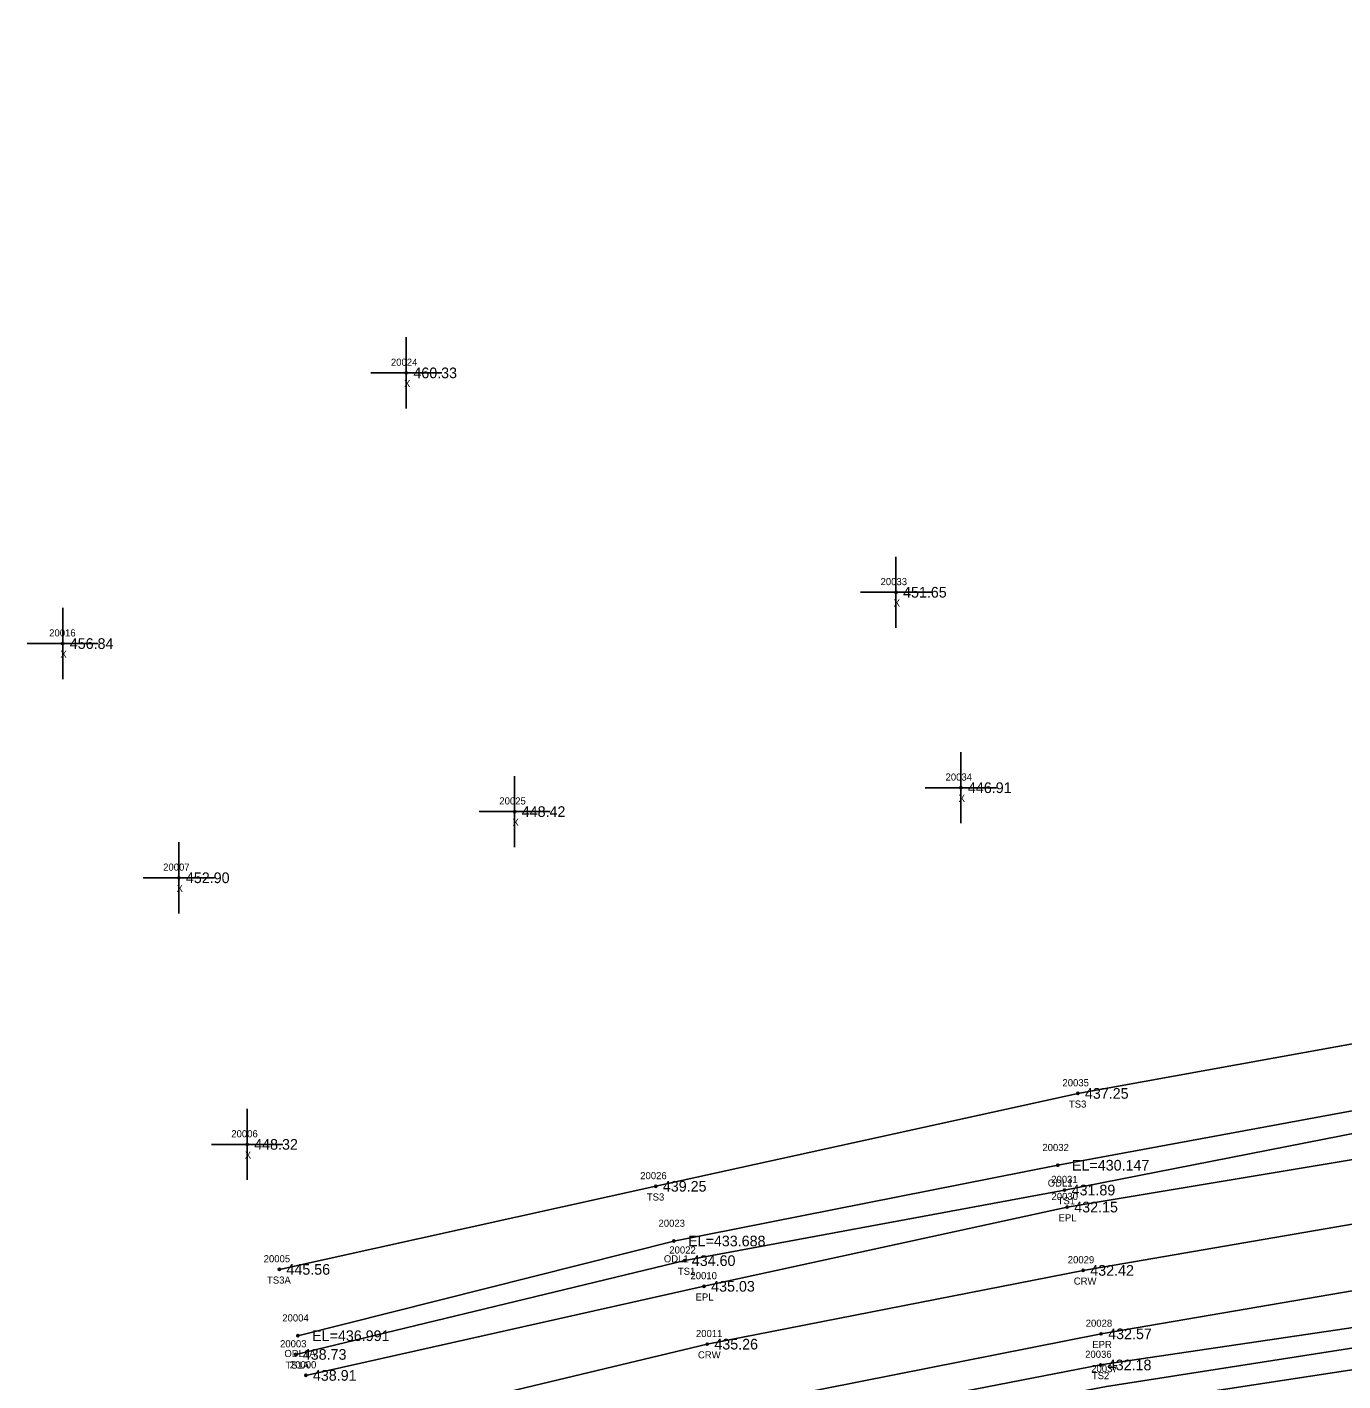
# Model space of a CAD drawing. Extents: x 2116373 to 2118139, y 979529 to 981026.
# Drawn here: x 2116373 to 2116558, y 979638.1 to 979828.4 of the extents above; entities that cross this region are included whole.
import ezdxf

# ---------------------------------------------------------------- set-up
doc = ezdxf.new("R2010")
doc.units = 0
for name, color, linetype in [('RD_DTM_BkLn1', 7, 'Continuous'), ('RD_DTM_BkLn2', 7, 'Continuous'), ('RD_DTM_BkLn_txCode', 7, 'Continuous'), ('RD_EX_H2O', 7, 'Continuous'), ('RD_EX_H2O_txCode', 7, 'Continuous'), ('RD_EX_Misc', 7, 'Continuous'), ('RD_EX_Misc_txCode', 7, 'Continuous'), ('RD_EX_Road', 7, 'Continuous'), ('RD_EX_Road_txCode', 7, 'Continuous'), ('RD_EX_TX_H2O_ELEV', 7, 'Continuous'), ('RD_EX_TX_Misc_ELEV', 7, 'Continuous'), ('RD_EX_TX_Road_ELEV', 7, 'Continuous'), ('RD_HC_Survey_ELEV', 7, 'Continuous'), ('RD_HC_Survey_txCode', 7, 'Continuous'), ('RD_SMD_Locator', 7, 'Continuous')]:
    doc.layers.add(name, color=color, linetype=linetype)

msp = doc.modelspace()

# ---------------------------------------------------------------- linework, layer by layer
at = {"layer": 'RD_DTM_BkLn1'}
msp.add_lwpolyline([(2116414.21, 979630.19), (2116468.62, 979643.23), (2116521.45, 979653.6), (2116618.87, 979670.38), (2116668.4, 979680.7), (2116717.3, 979694.48), (2116764.56, 979711.13), (2116810.15, 979729.38), (2116856.49, 979749.81), (2116900.74, 979773.15), (2116944.03, 979798.93), (2116982.75, 979824.6), (2117026.56, 979857.02), (2117064.34, 979888.81), (2117101.78, 979922.69), (2117176.3, 979989.4), (2117250.99, 980056.19), (2117326.56, 980126.36)], dxfattribs=at)
at = {"layer": 'RD_DTM_BkLn2'}
for points in [[(2116410.78, 979641.79), (2116465.45, 979654.97), (2116518.83, 979664.89), (2116614.96, 979683.75), (2116663.75, 979692.58), (2116713.02, 979705.22), (2116760.07, 979721.97), (2116804.88, 979741.47), (2116850.79, 979761.38), (2116894.83, 979783.88), (2116937.98, 979807.44), (2116977.39, 979833.6), (2117020.56, 979865.29), (2117056.86, 979896.38), (2117094.29, 979932.2), (2117168.14, 979997.38), (2117238.71, 980069.61), (2117312.33, 980134.21), (2117318.43, 980135.16)], [(2116408.48, 979653.74), (2116461.38, 979665.42), (2116520.7, 979678.48), (2116616.28, 979695.74), (2116661.37, 979703.79), (2116711.18, 979715.21), (2116757.77, 979732.03), (2116802.04, 979749.54), (2116847.76, 979769.63), (2116889.13, 979795.82), (2116931.32, 979820.72), (2116972.01, 979847.71), (2117009.67, 979877.33), (2117051.05, 979910.18), (2117086.71, 979942.74), (2117161.4, 980003.96), (2117222.13, 980080.24), (2117265.44, 980120.03)], [(2116417.57, 979618.2), (2116471.29, 979630.11), (2116523.91, 979640.31), (2116563.87, 979646.21), (2116622.92, 979650.9), (2116673.37, 979660.68), (2116721.38, 979672.44), (2116775.31, 979687.3), (2116820.23, 979708.52), (2116865.35, 979734.51), (2116907.21, 979760.29), (2116934.42, 979772.82), (2116951.5, 979788.78), (2116990.39, 979814.35), (2117033.97, 979847.22), (2117071.26, 979879.46), (2117111.32, 979914.45), (2117184.14, 979980.37), (2117264.18, 980040.84), (2117335.34, 980108.05), (2117336.43, 980115.6)], [(2116420.33, 979611.17), (2116472.25, 979624.85), (2116526.15, 979634.55), (2116564.74, 979640.45), (2116627.58, 979623.31), (2116680.58, 979618.75), (2116744.33, 979647.79), (2116783.58, 979660.27), (2116799.87, 979666.49), (2116808.73, 979670.75)]]:
    msp.add_lwpolyline(points, dxfattribs=at)
at = {"layer": 'RD_EX_H2O'}
for points in [[(2116411.09, 979644.42), (2116463.93, 979657.73), (2116517.88, 979668.38), (2116615.09, 979686.35), (2116663.35, 979695.16), (2116711.62, 979708.91), (2116758.49, 979726.13), (2116778.25, 979736.27), (2116803.5, 979744.47), (2116849.89, 979764.23), (2116894.14, 979786.32), (2116936.31, 979809.39), (2116976.21, 979834.9), (2117018.41, 979867.86), (2117054.24, 979898.91), (2117093.35, 979934.14), (2117166.11, 979999.69), (2117224.07, 980077.92), (2117265.44, 980120.03)], [(2116419.35, 979615.24), (2116471.51, 979627.15), (2116524.74, 979637.29), (2116564.01, 979643.4), (2116629.25, 979631.55), (2116678.97, 979635.46), (2116738.46, 979663.21), (2116776.82, 979674.03), (2116792.52, 979682.03), (2116799, 979683.75), (2116807.27, 979675.26), (2116829.37, 979675.94), (2116879.68, 979679.78), (2116933.5, 979668.89), (2116988.71, 979660.02), (2117093.78, 979621.95), (2117143.56, 979603.85), (2117167, 979599.31)]]:
    msp.add_lwpolyline(points, dxfattribs=at)
at = {"layer": 'RD_EX_Misc'}
for p, q in [((2116426.32, 979774.76), (2116426.32, 979784.76)), ((2116421.32, 979779.76), (2116431.32, 979779.76)), ((2116495.14, 979743.92), (2116495.14, 979753.92)), ((2116490.14, 979748.92), (2116500.14, 979748.92)), ((2116378.03, 979736.71), (2116378.03, 979746.71)), ((2116373.03, 979741.71), (2116383.03, 979741.71)), ((2116504.26, 979716.45), (2116504.26, 979726.45)), ((2116441.55, 979713.09), (2116441.55, 979723.09)), ((2116499.26, 979721.45), (2116509.26, 979721.45)), ((2116436.55, 979718.09), (2116446.55, 979718.09)), ((2116394.35, 979703.79), (2116394.35, 979713.79)), ((2116389.35, 979708.79), (2116399.35, 979708.79)), ((2116403.95, 979666.31), (2116403.95, 979676.31)), ((2116398.95, 979671.31), (2116408.95, 979671.31))]:
    msp.add_line(p, q, dxfattribs=at)
at = {"layer": 'RD_EX_Road'}
for points in [[(2116412.2, 979638.84), (2116468.17, 979651.36), (2116519.2, 979662.5), (2116617.24, 979678.85), (2116665.51, 979689.1), (2116714.23, 979702.46), (2116761.42, 979719.35), (2116806.99, 979737.42), (2116852.23, 979758.11), (2116896.57, 979780.91), (2116939.1, 979805.52), (2116978.46, 979832.1), (2117021.29, 979863.87), (2117058.15, 979895.61), (2117096.06, 979930.47), (2117170.14, 979995.71), (2117244.91, 980062.82), (2117320.63, 980133.49), (2117326.56, 980126.36)], [(2116416.36, 979621.21), (2116470.51, 979634.11), (2116523.97, 979644.68), (2116620.55, 979661.21), (2116670.7, 979671.96), (2116720.65, 979685.84), (2116767.66, 979702.22), (2116814.07, 979721.02), (2116860.35, 979742.3), (2116904.9, 979765.18), (2116949.06, 979791.19), (2116988.09, 979817.15), (2117031.94, 979849.78), (2117069.79, 979881.53), (2117108.89, 979916.38), (2117182.06, 979982.67), (2117257.56, 980049.29), (2117334.73, 980117.38), (2117326.56, 980126.36)]]:
    msp.add_lwpolyline(points, dxfattribs=at)
at = {"layer": 'RD_SMD_Locator'}
for centre in [(2116426.32, 979779.76), (2116495.14, 979748.92), (2116378.03, 979741.71), (2116504.26, 979721.45), (2116441.55, 979718.09), (2116394.35, 979708.79), (2116520.7, 979678.48), (2116403.95, 979671.31), (2116517.88, 979668.38), (2116461.38, 979665.42), (2116518.83, 979664.89), (2116519.2, 979662.5), (2116463.93, 979657.73), (2116465.45, 979654.97), (2116408.48, 979653.74), (2116521.45, 979653.6), (2116468.17, 979651.36), (2116411.09, 979644.42), (2116468.62, 979643.23), (2116523.97, 979644.68), (2116410.78, 979641.79), (2116523.91, 979640.31), (2116412.2, 979638.84)]:
    msp.add_circle(centre, 0.15, dxfattribs=at)

# ---------------------------------------------------------------- texts
at = {"layer": 'RD_DTM_BkLn_txCode'}
for s, p in [('20035', (2116518.54, 979679.48)), ('TS3', (2116519.45, 979676.48)), ('20026', (2116459.2, 979666.42)), ('20031', (2116516.96, 979665.89)), ('TS3', (2116460.13, 979663.42)), ('TS1', (2116517.87, 979662.89)), ('20022', (2116463.29, 979655.97)), ('20005', (2116406.28, 979654.74)), ('TS1', (2116464.49, 979652.97)), ('TS3A', (2116406.75, 979651.74)), ('20003', (2116408.58, 979642.79)), ('20036', (2116521.73, 979641.31)), ('TS1A', (2116409.33, 979639.79)), ('TS2', (2116522.67, 979638.31))]:
    msp.add_text(s, height=1, dxfattribs=at).set_placement(p)
at = {"layer": 'RD_EX_H2O_txCode'}
for s, p in [('20032', (2116515.72, 979670.38)), ('ODL1', (2116516.47, 979665.38)), ('20023', (2116461.77, 979659.73)), ('ODL1', (2116462.52, 979654.73)), ('20004', (2116408.89, 979646.42)), ('ODL1A', (2116409.19, 979641.42)), ('20037', (2116522.58, 979639.29))]:
    msp.add_text(s, height=1, dxfattribs=at).set_placement(p)
at = {"layer": 'RD_EX_Misc_txCode'}
for s, p in [('20024', (2116424.16, 979780.76)), ('X', (2116426, 979777.76)), ('20033', (2116492.98, 979749.92)), ('X', (2116494.82, 979746.92)), ('20016', (2116376.13, 979742.71)), ('X', (2116377.71, 979739.71)), ('20034', (2116502.11, 979722.45)), ('20025', (2116439.4, 979719.09)), ('X', (2116503.95, 979719.45)), ('X', (2116441.24, 979716.09)), ('20007', (2116392.15, 979709.79)), ('X', (2116394.04, 979706.79)), ('20006', (2116401.73, 979672.31)), ('X', (2116403.63, 979669.31))]:
    msp.add_text(s, height=1, dxfattribs=at).set_placement(p)
at = {"layer": 'RD_EX_Road_txCode'}
for s, p in [('20030', (2116517, 979663.5)), ('EPL', (2116517.99, 979660.5)), ('20010', (2116466.26, 979652.36)), ('EPL', (2116466.97, 979649.36)), ('20028', (2116521.81, 979645.68)), ('EPR', (2116522.74, 979642.68)), ('20000', (2116409.96, 979639.84))]:
    msp.add_text(s, height=1, dxfattribs=at).set_placement(p)
at = {"layer": 'RD_EX_TX_H2O_ELEV'}
for s, p in [('EL=430.147', (2116519.88, 979667.63)), ('EL=433.688', (2116465.93, 979656.98)), ('EL=436.991', (2116413.09, 979643.67))]:
    msp.add_text(s, height=1.5, dxfattribs=at).set_placement(p)
at = {"layer": 'RD_EX_TX_Misc_ELEV'}
for s, p in [('460.33', (2116427.32, 979779.01)), ('451.65', (2116496.14, 979748.17)), ('456.84', (2116379.03, 979740.96)), ('446.91', (2116505.26, 979720.7)), ('448.42', (2116442.55, 979717.34)), ('452.90', (2116395.35, 979708.04)), ('437.25', (2116521.7, 979677.73)), ('448.32', (2116404.95, 979670.56)), ('439.25', (2116462.38, 979664.67)), ('431.89', (2116519.83, 979664.14)), ('434.60', (2116466.45, 979654.22)), ('445.56', (2116409.48, 979652.99)), ('438.73', (2116411.78, 979641.04)), ('432.18', (2116524.91, 979639.56))]:
    msp.add_text(s, height=1.5, dxfattribs=at).set_placement(p)
at = {"layer": 'RD_EX_TX_Road_ELEV'}
for s, p in [('432.15', (2116520.2, 979661.75)), ('435.03', (2116469.17, 979650.61)), ('432.57', (2116524.97, 979643.93)), ('438.91', (2116413.2, 979638.09))]:
    msp.add_text(s, height=1.5, dxfattribs=at).set_placement(p)
at = {"layer": 'RD_HC_Survey_ELEV'}
for s, p in [('432.42', (2116522.45, 979652.85)), ('435.26', (2116469.62, 979642.48))]:
    msp.add_text(s, height=1.5, dxfattribs=at).set_placement(p)
at = {"layer": 'RD_HC_Survey_txCode'}
for s, p in [('20029', (2116519.29, 979654.6)), ('CRW', (2116520.13, 979651.6)), ('20011', (2116467.03, 979644.23)), ('CRW', (2116467.31, 979641.23))]:
    msp.add_text(s, height=1, dxfattribs=at).set_placement(p)

doc.saveas('drawing.dxf')
